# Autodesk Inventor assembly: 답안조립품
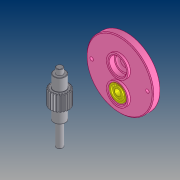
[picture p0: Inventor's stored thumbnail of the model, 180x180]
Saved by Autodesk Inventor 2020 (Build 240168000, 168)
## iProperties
Created: 2020-07
Part Number: 답안조립품
Document SubType Name: Assembly
Designer: PC312-
Author: PC312-
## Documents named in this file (5)
- C:\Users\PC312-\Desktop\700718V1002 (4)\답안조립품.iam
- C:\Users\PC312-\Desktop\700718V1002 (4)\본체.ipt
- C:\Users\PC312-\Desktop\700718V1002 (4)\커버.ipt
- C:\Users\PC312-\Desktop\700718V1002 (4)\메인 축.ipt
- C:\Users\PC312-\Desktop\700718V1002 (4)\베어링 608.ipt
